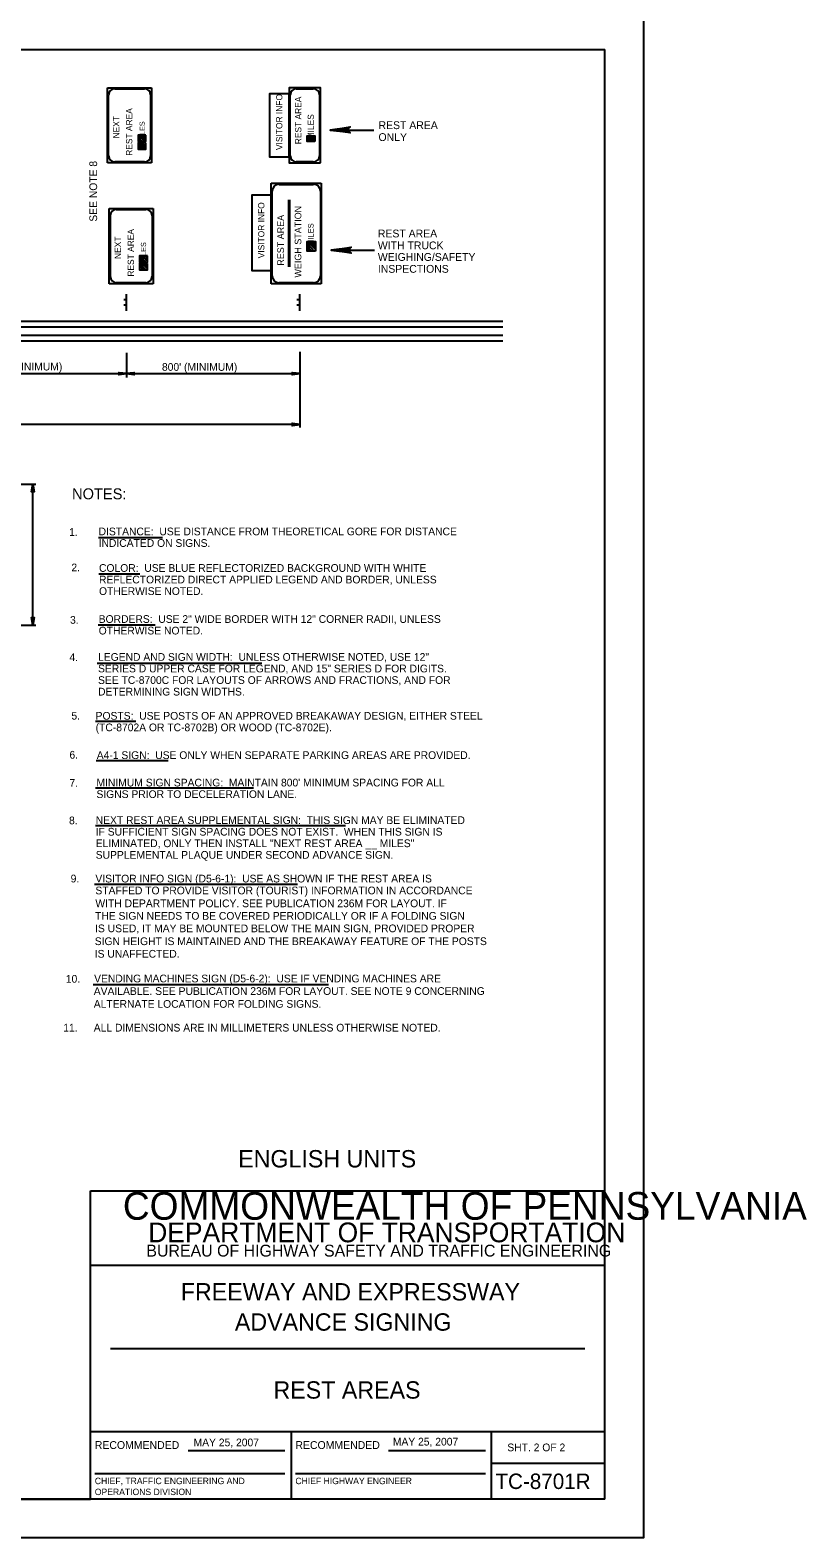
# Model space of a CAD drawing. Extents: x 649604 to 650509, y 298458 to 299646.
# Drawn here: x 650207 to 650509, y 298458 to 299044 of the extents above; entities that cross this region are included whole.
import ezdxf

# ---------------------------------------------------------------- set-up
doc = ezdxf.new("R2010")
doc.units = 0
for name, color, linetype in [('1', 7, 'Continuous'), ('2', 7, 'Continuous'), ('3', 7, 'Continuous'), ('PLT-BNDY', 7, 'Continuous')]:
    doc.layers.add(name, color=color, linetype=linetype)

# ---------------------------------------------------------------- blocks, each defined once
blk = doc.blocks.new('RARROW')
at = {"layer": '3'}
blk.add_lwpolyline([(-2.2695, 0.285), (-2.184875, 0.12075), (0, 0), (-2.2695, 0.285), (-2.38575, 0.384625), (0, 0), (-2.183125, -0.108), (-2.262875, -0.2705), (0, 0), (-2.38575, -0.379125), (-2.262875, -0.2705)], dxfattribs=at)

msp = doc.modelspace()

# ---------------------------------------------------------------- linework, layer by layer
at = {"layer": '1'}
for p, q in [((649644.31, 299036.63), (650430.31, 299036.63)), ((650430.31, 298472.63), (650430.31, 299036.63)), ((650230.31, 298472.63), (650230.31, 298592.63)), ((650230.31, 298592.63), (650430.31, 298592.63)), ((650430.31, 298563.63), (650230.31, 298563.63)), ((650238.06, 298531.31), (650422.56, 298531.31)), ((650230.31, 298499), (650430.31, 298499)), ((650308.31, 298499), (650308.31, 298472.63)), ((650386.19, 298472.63), (650386.19, 298499)), ((650268.24, 298491.57), (650305.87, 298491.57)), ((650346.24, 298491.57), (650383.87, 298491.57)), ((650231.99, 298482.68), (650305.87, 298482.68)), ((650309.99, 298482.68), (650383.87, 298482.68)), ((650386.19, 298486.63), (650430.31, 298486.63)), ((650430.31, 298472.63), (649644.31, 298472.63)), ((649644.31, 298472.63), (650230.31, 298472.63))]:
    msp.add_line(p, q, dxfattribs=at)
at = {"layer": '2'}
for p, q in [((650236.94, 298992.5), (650236.94, 299021.75)), ((650236.94, 299021.75), (650254.06, 299021.75)), ((650239.81, 299021.25), (650251.31, 299021.25)), ((650254.06, 299021.75), (650254.06, 298992.5)), ((650310.31, 299021.25), (650316.94, 299021.25)), ((650237.31, 298995.25), (650237.31, 299018.88)), ((650253.69, 299018.88), (650253.69, 298995.25)), ((650323.56, 299005.25), (650340.44, 299005.25)), ((650254.06, 298992.5), (650236.94, 298992.5)), ((650251.31, 298992.88), (650239.81, 298992.88)), ((650300.56, 298945.5), (650300.56, 298984.63)), ((650300.94, 298948.5), (650300.94, 298981.63)), ((650303.56, 298984.13), (650317.06, 298984.13)), ((650319.69, 298981.63), (650319.69, 298948.5)), ((650320.06, 298984.63), (650320.06, 298945.5)), ((650237.56, 298945.5), (650237.56, 298974.75)), ((650237.56, 298974.75), (650254.69, 298974.75)), ((650240.31, 298974.38), (650251.81, 298974.38)), ((650254.69, 298974.75), (650254.69, 298945.5)), ((650307.44, 298952), (650307.44, 298978.13)), ((650307.56, 298952), (650307.56, 298978.13)), ((650307.69, 298952), (650307.69, 298978.13)), ((650307.81, 298952), (650307.81, 298978.13)), ((650307.81, 298952), (650307.81, 298978.13)), ((650238.06, 298948.25), (650238.06, 298971.88)), ((650254.31, 298971.88), (650254.31, 298948.25)), ((650323.94, 298958.5), (650340.81, 298958.5)), ((650254.69, 298945.5), (650237.56, 298945.5)), ((650251.81, 298945.88), (650240.31, 298945.88)), ((650244.31, 298939.25), (650243.31, 298939.25)), ((650244.31, 298935), (650244.31, 298941.38)), ((650311.69, 298939.25), (650310.56, 298939.25)), ((650311.69, 298935), (650311.69, 298941.38)), ((650244.31, 298937.13), (650243.31, 298937.13)), ((650311.69, 298937.13), (650310.56, 298937.13)), ((649664.19, 298928.75), (650390.69, 298928.75)), ((649946.56, 298930.88), (650390.69, 298930.88)), ((650330.44, 298930.88), (650330.44, 298930.88)), ((649664.19, 298925.5), (650390.69, 298925.5)), ((649664.19, 298923.25), (650390.69, 298923.25)), ((650244.31, 298918.63), (650244.31, 298909)), ((650311.69, 298919), (650311.69, 298889.5)), ((650176.94, 298910.5), (650244.31, 298910.5)), ((650244.31, 298910.5), (650311.69, 298910.5)), ((650311.69, 298890.75), (649881.31, 298890.75)), ((650181.27, 298867.5), (650209, 298867.5)), ((650207.88, 298812.63), (650207.88, 298867.5)), ((650233.42, 298846.75), (650258.31, 298846.75)), ((650233.57, 298832.66), (650249.5, 298832.66)), ((650181.27, 298812.63), (650209, 298812.63)), ((650233.32, 298812.8), (650255.5, 298812.8)), ((650232.96, 298797.93), (650297, 298797.93)), ((650232.22, 298775.29), (650247.93, 298775.29)), ((650232.57, 298759.98), (650260.48, 298759.98)), ((650232.31, 298749.4), (650293.65, 298749.4)), ((650232.3, 298734.76), (650329.5, 298734.76)), ((650231.91, 298711.95), (650310.87, 298711.95)), ((650231.31, 298672.83), (650322.82, 298672.83))]:
    msp.add_line(p, q, dxfattribs=at)
for points in [[(650319.81, 298992.5), (650319.81, 299021.75), (650307.56, 299021.75), (650307.56, 298992.5)], [(650307.56, 298994.88), (650307.56, 299019.38), (650299.94, 299019.38), (650299.94, 298994.88)], [(650251.81, 299003.25), (650248.81, 299003.25), (650248.81, 299000.88), (650251.81, 299000.88)], [(650251.81, 299000.25), (650248.81, 299000.25), (650248.81, 298997.88), (650251.81, 298997.88)], [(650317.56, 299000.75), (650314.56, 299000.75), (650314.56, 299003), (650317.56, 299003)], [(650300.56, 298950.63), (650300.56, 298980), (650293.06, 298980), (650293.06, 298950.63)], [(650317.81, 298958.13), (650314.56, 298958.13), (650314.56, 298961.88), (650317.81, 298961.88)], [(650252.44, 298956.38), (650249.31, 298956.38), (650249.31, 298953.88), (650252.44, 298953.88)], [(650252.44, 298953.38), (650249.31, 298953.38), (650249.31, 298950.88), (650252.44, 298950.88)]]:
    msp.add_lwpolyline(points, close=True, dxfattribs=at)
for points in [[(650307.94, 298995.25), (650307.94, 299018.88)], [(650319.31, 299018.88), (650319.31, 298995.25)], [(650331.06, 299004.38), (650330.69, 299005), (650323.56, 299005.25), (650331.06, 299004.38), (650331.31, 299004.13), (650323.56, 299005.25), (650330.69, 299005.75), (650330.94, 299006.25), (650323.56, 299005.25), (650331.31, 299006.5), (650330.94, 299006.25)], [(650251.31, 299000.88), (650248.81, 299003.25)], [(650250.31, 299000.88), (650248.81, 299002.5)], [(650249.44, 299000.88), (650248.81, 299001.75)], [(650251.31, 298997.88), (650248.81, 299000.25)], [(650250.31, 298997.88), (650248.81, 298999.5)], [(650249.44, 298997.88), (650248.81, 298998.5)], [(650251.81, 298998.13), (650249.56, 299000.25)], [(650251.81, 299001.13), (650249.69, 299003.25)], [(650251.81, 299002), (650250.44, 299003.25)], [(650251.81, 298998.88), (650250.44, 299000.25)], [(650251.81, 299003), (650251.44, 299003.25)], [(650251.81, 298999.88), (650251.44, 299000.25)], [(650316.81, 299000.75), (650314.56, 299003)], [(650316.31, 299000.75), (650314.56, 299002.5)], [(650315.81, 299000.75), (650314.56, 299002)], [(650315.44, 299000.75), (650314.56, 299001.63)], [(650314.94, 299000.75), (650314.56, 299001.13)], [(650317.19, 299000.75), (650314.81, 299003)], [(650317.56, 299000.88), (650315.19, 299003)], [(650317.56, 299001.38), (650315.69, 299003)], [(650317.56, 299001.88), (650316.19, 299003)], [(650317.56, 299002.25), (650316.69, 299003)], [(650317.56, 299002.75), (650317.06, 299003)], [(650316.94, 298992.88), (650310.31, 298992.88)], [(650300.56, 298984.63), (650302.94, 298984.63), (650305.56, 298984.63), (650307.69, 298984.63), (650309.69, 298984.63), (650312.31, 298984.63), (650314.56, 298984.63), (650315.06, 298984.63), (650317.06, 298984.63), (650317.81, 298984.63), (650320.06, 298984.63)], [(650317.81, 298958.75), (650314.56, 298961.88)], [(650317.31, 298958.13), (650314.56, 298961.13)], [(650316.44, 298958.13), (650314.56, 298960.13)], [(650315.56, 298958.13), (650314.56, 298959.25)], [(650314.56, 298958.13), (650314.56, 298958.25)], [(650317.81, 298959.63), (650315.44, 298961.88)], [(650317.81, 298960.5), (650316.44, 298961.88)], [(650317.81, 298961.5), (650317.31, 298961.88)], [(650331.31, 298957.63), (650331.19, 298958.13), (650323.94, 298958.5), (650331.31, 298957.63), (650331.69, 298957.38), (650323.94, 298958.5), (650331.19, 298959), (650331.31, 298959.5), (650323.94, 298958.5), (650331.69, 298959.75), (650331.31, 298959.5)], [(650251.81, 298953.88), (650249.31, 298956.38)], [(650251.06, 298953.88), (650249.31, 298955.5)], [(650250.19, 298953.88), (650249.31, 298954.75)], [(650251.81, 298950.88), (650249.31, 298953.38)], [(650251.06, 298950.88), (650249.31, 298952.5)], [(650250.19, 298950.88), (650249.31, 298951.5)], [(650252.44, 298954.25), (650250.31, 298956.38)], [(650252.44, 298951.25), (650250.31, 298953.38)], [(650252.44, 298955.13), (650251.19, 298956.38)], [(650252.44, 298952), (650251.19, 298953.38)], [(650252.44, 298955.88), (650252.06, 298956.38)], [(650252.44, 298952.88), (650252.06, 298953.38)], [(650320.06, 298945.5), (650300.56, 298945.5)], [(650317.06, 298945.88), (650303.56, 298945.88)]]:
    msp.add_lwpolyline(points, dxfattribs=at)
for centre, radius, start, end in [((650239.81, 299018.91), 2.44, 90, 180), ((650251.22, 299018.91), 2.44, 0, 90), ((650310.4, 299018.91), 2.44, 90, 180), ((650316.92, 299018.91), 2.44, 0, 90), ((650239.81, 298995.29), 2.44, 180, 270), ((650251.22, 298995.29), 2.44, 270, 0), ((650310.4, 298995.29), 2.44, 180, 270), ((650316.92, 298995.29), 2.44, 270, 0), ((650303.6, 298981.54), 2.61, 90, 180), ((650317.08, 298981.54), 2.61, 0, 90), ((650240.41, 298971.93), 2.44, 90, 180), ((650251.82, 298971.93), 2.44, 0, 90), ((650240.41, 298948.3), 2.44, 180, 270), ((650251.82, 298948.3), 2.44, 270, 0), ((650303.6, 298948.5), 2.61, 180, 270), ((650317.08, 298948.5), 2.61, 270, 0)]:
    msp.add_arc(centre, radius, start, end, dxfattribs=at)
at = {"layer": 'PLT-BNDY'}
msp.add_lwpolyline([(649604.31, 299051.63), (650445.31, 299051.63), (650445.31, 298457.63), (649604.31, 298457.63)], close=True, dxfattribs=at)

# ---------------------------------------------------------------- block references
at = {"layer": '2', "xscale": 1.2574347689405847, "yscale": 1.3092961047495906}
for p in [(650244.31, 298910.5), (650311.69, 298910.5), (650311.69, 298890.75)]:
    msp.add_blockref('RARROW', p, dxfattribs=at)
for p, rotation in [((650244.31, 298910.5), 180), ((650207.88, 298867.5), 89.99999999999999), ((650207.88, 298812.63), -90.00000000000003)]:
    msp.add_blockref('RARROW', p, dxfattribs=dict(at, rotation=rotation))

# ---------------------------------------------------------------- texts
at = {"layer": '1'}
for s, height, p in [('COMMONWEALTH OF PENNSYLVANIA', 10.7828, (650242.9, 298581.36)), ('DEPARTMENT OF TRANSPORTATION', 7.6837, (650252.76, 298572.61)), ('BUREAU OF HIGHWAY SAFETY AND TRAFFIC ENGINEERING', 4.6253, (650252.04, 298567.04)), ('FREEWAY AND EXPRESSWAY', 6.75, (650265.42, 298549.97)), ('ADVANCE SIGNING', 6.75, (650286.45, 298538.22)), ('REST AREAS', 6.75, (650301.47, 298511.78)), ('RECOMMENDED', 3.048, (650231.99, 298492.2)), ('RECOMMENDED', 3.048, (650309.99, 298492.2)), ('SHT. 2 OF 2', 3, (650392.4, 298491.31)), ('TC-8701R', 6, (650387.77, 298476.63)), ('OPERATIONS DIVISION', 2.5, (650231.99, 298474.26)), ('CHIEF, TRAFFIC ENGINEERING AND', 2.5, (650231.99, 298478.51)), ('CHIEF HIGHWAY ENGINEER', 2.5, (650309.99, 298478.51))]:
    msp.add_text(s, height=height, dxfattribs=at).set_placement(p)
at = {"layer": '2'}
for s, height, p in [('VISITOR INFO', 2.4443, (650304.94, 298997.5)), ('REST AREA', 2.444, (650312.31, 298999.75)), ('NEXT', 2.443, (650241.56, 299002)), ('REST AREA', 2.443, (650246.56, 298995.25)), ('    MILES', 2.443, (650317.19, 298998)), ('   MILES', 2.035, (650251.44, 298997.88)), ('SEE NOTE 8', 3, (650232.89, 298969.63)), ('VISITOR INFO', 2.4443, (650297.94, 298955.38)), ('WEIGH STATION', 2.6078, (650312.31, 298947.88)), ('REST AREA', 2.608, (650305.56, 298952.5)), ('  MILES', 2.174, (650317.06, 298958.63)), ('NEXT', 2.443, (650242.19, 298955.13)), ('REST AREA', 2.443, (650247.19, 298948.25)), ('   MILES', 2.035, (650251.94, 298950.88))]:
    msp.add_text(s, height=height, rotation=90, dxfattribs=at).set_placement(p)
for s, height, p in [('ONLY', 3.041, (650342.31, 299001)), ('REST AREA', 3.041, (650342.31, 299005.63)), ('REST AREA', 3.041, (650342.06, 298963.5)), ('WITH TRUCK', 3.041, (650342.06, 298958.88)), ('WEIGHING/SAFETY', 3.0405, (650342.06, 298954.38)), ('INSPECTIONS', 3.0405, (650342.06, 298949.75)), ("800' (MINIMUM)", 3, (650190.06, 298911.75)), ("800' (MINIMUM)", 3, (650258.1, 298911.61)), ('NOTES:', 4.25, (650223.15, 298861.63)), ('1.  ', 3, (650222, 298847.41)), ('DISTANCE:  USE DISTANCE FROM THEORETICAL GORE FOR DISTANCE', 3, (650233.47, 298847.62)), ('INDICATED ON SIGNS.', 3, (650233.47, 298843.12)), ('2.  ', 3, (650222.89, 298833.61)), ('COLOR:  USE BLUE REFLECTORIZED BACKGROUND WITH WHITE', 3, (650233.63, 298833.41)), ('REFLECTORIZED DIRECT APPLIED LEGEND AND BORDER, UNLESS', 3, (650233.63, 298828.91)), ('OTHERWISE NOTED.', 3, (650233.63, 298824.41)), ('3.  ', 3, (650222.38, 298813.21)), ('BORDERS:  USE 2" WIDE BORDER WITH 12" CORNER RADII, UNLESS ', 3, (650233.5, 298813.55)), ('OTHERWISE NOTED.', 3, (650233.5, 298809.05)), ('4.', 3, (650222.13, 298798.69)), ('LEGEND AND SIGN WIDTH:  UNLESS OTHERWISE NOTED, USE 12"', 3, (650233.25, 298798.8)), ('SERIES D UPPER CASE FOR LEGEND, AND 15" SERIES D FOR DIGITS.', 3, (650233.25, 298794.3)), ('SEE TC-8700C FOR LAYOUTS OF ARROWS AND FRACTIONS, AND FOR ', 3, (650233.25, 298789.8)), ('DETERMINING SIGN WIDTHS.', 3, (650233.25, 298785.3)), ('5.  ', 3, (650222.89, 298775.93)), ('POSTS:  USE POSTS OF AN APPROVED BREAKAWAY DESIGN, EITHER STEEL', 3, (650232.31, 298775.9)), ('(TC-8702A OR TC-8702B) OR WOOD (TC-8702E).', 3, (650232.31, 298771.4)), ('6.  ', 3, (650222.14, 298760.74)), ('A4-1 SIGN:  USE ONLY WHEN SEPARATE PARKING AREAS ARE PROVIDED.', 3, (650232.75, 298760.6)), ('7.  ', 3, (650222.12, 298749.81)), ("MINIMUM SIGN SPACING:  MAINTAIN 800' MINIMUM SPACING FOR ALL", 3, (650232.63, 298749.93)), ('SIGNS PRIOR TO DECELERATION LANE.', 3, (650232.63, 298745.43)), ('8.  ', 3, (650221.97, 298735.21)), ('NEXT REST AREA SUPPLEMENTAL SIGN:  THIS SIGN MAY BE ELIMINATED', 3, (650232.34, 298735.31)), ('IF SUFFICIENT SIGN SPACING DOES NOT EXIST.  WHEN THIS SIGN IS', 3, (650232.34, 298730.81)), ('ELIMINATED, ONLY THEN INSTALL "NEXT REST AREA __ MILES" ', 3, (650232.34, 298726.31)), ('SUPPLEMENTAL PLAQUE UNDER SECOND ADVANCE SIGN.', 3, (650232.34, 298721.81)), ('9.  ', 3, (650222.6, 298712.59)), ('VISITOR INFO SIGN (D5-6-1):  USE AS SHOWN IF THE REST AREA IS', 3, (650232.22, 298712.58)), ('STAFFED TO PROVIDE VISITOR (TOURIST) INFORMATION IN ACCORDANCE', 3, (650232.22, 298707.96)), ('WITH DEPARTMENT POLICY. SEE PUBLICATION 236M FOR LAYOUT. IF', 3, (650232.22, 298702.95)), ('THE SIGN NEEDS TO BE COVERED PERIODICALLY OR IF A FOLDING SIGN', 3, (650232.09, 298698.08)), ('IS USED, IT MAY BE MOUNTED BELOW THE MAIN SIGN, PROVIDED PROPER', 3, (650232.09, 298693.21)), ('SIGN HEIGHT IS MAINTAINED AND THE BREAKAWAY FEATURE OF THE POSTS', 3, (650231.97, 298688.21)), ('IS UNAFFECTED.', 3, (650231.97, 298683.33)), ('10.   ', 3, (650220.71, 298673.59)), ('VENDING MACHINES SIGN (D5-6-2):  USE IF VENDING MACHINES ARE', 3, (650231.72, 298673.71)), ('AVAILABLE. SEE PUBLICATION 236M FOR LAYOUT. SEE NOTE 9 CONCERNING', 3, (650231.59, 298668.83)), ('ALTERNATE LOCATION FOR FOLDING SIGNS.', 3, (650231.59, 298663.83)), ('11. ', 3, (650219.72, 298654.58)), ('ALL DIMENSIONS ARE IN MILLIMETERS UNLESS OTHERWISE NOTED.', 3, (650231.59, 298654.58)), ('ENGLISH UNITS', 6.75, (650287.74, 298601.72)), ('MAY 25, 2007', 3, (650270.4, 298493.24)), ('MAY 25, 2007', 3, (650347.88, 298493.54))]:
    msp.add_text(s, height=height, dxfattribs=at).set_placement(p)

doc.saveas('drawing.dxf')
